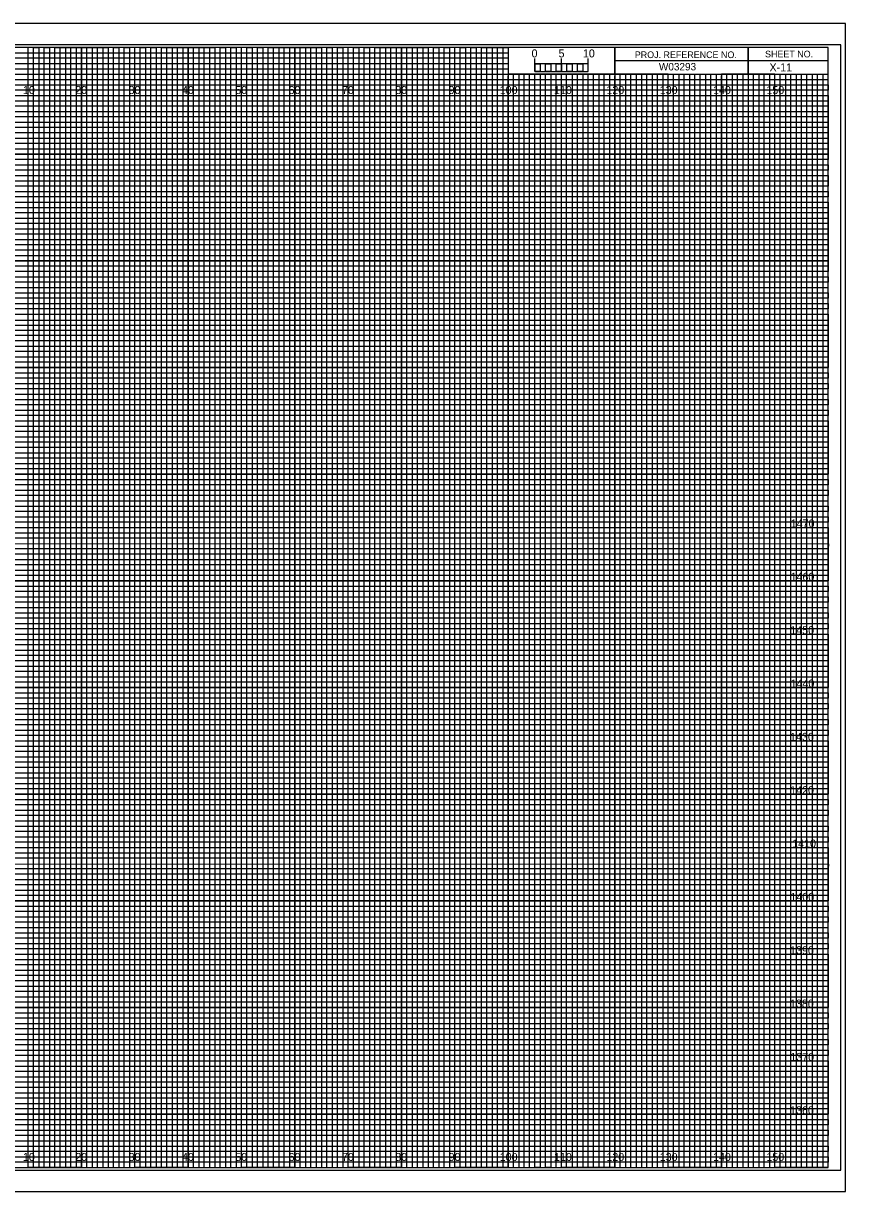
# Model space of a CAD drawing. Extents: x -13 to 323, y -5 to 215.
# Drawn here: x 169.1 to 323.3, y -4.5 to 214.5 of the extents above; entities that cross this region are included whole.
import ezdxf

# ---------------------------------------------------------------- set-up
doc = ezdxf.new("R2010")
doc.units = 0
for name, color, linetype in [('Exist Cross Section Cell', 7, 'Continuous'), ('Exist XS Center Line Elevation Label', 7, 'Continuous'), ('Exist XS Ground Line', 7, 'Continuous'), ('Prop XS EOT Tick Mark', 7, 'Continuous'), ('Prop XS Finish Grade', 7, 'Continuous'), ('Prop XS Finish Grade Pavement', 7, 'Continuous'), ('Prop XS Retaining Wall', 7, 'Continuous'), ('Prop XS SE Text', 7, 'Continuous'), ('Prop XS Side Slope Text', 7, 'Continuous'), ('Prop XS SS Elevation Text', 7, 'Continuous'), ('Prop XS Subgrade Earthwork', 7, 'Continuous'), ('Prop XSC Text', 7, 'Continuous'), ('Scratch_Level_0', 7, 'Continuous'), ('Scratch_Level_5', 7, 'Continuous'), ('Typical Curb CELL', 7, 'Continuous')]:
    doc.layers.add(name, color=color, linetype=linetype)

msp = doc.modelspace()

# ---------------------------------------------------------------- linework, layer by layer
at = {"layer": 'Exist Cross Section Cell'}
for points in [[(165, 0), (175, 0), (175, 210), (185, 210), (185, 0), (195, 0), (195, 210), (205, 210), (205, 0), (215, 0), (215, 210), (225, 210), (225, 0), (235, 0), (235, 210), (245, 210), (245, 0), (255, 0), (255, 210), (259.93, 210), (260, 210), (260, 205), (264.99, 205), (264.99, 0), (275, 0), (275, 205), (285, 205), (285, 0), (295, 0), (295, 205), (305, 205), (305, 0), (315, 0), (315, 205)], [(0, 205), (275, 205)], [(0, 185), (320, 185), (320, 195), (0, 195)], [(0, 165), (320, 165), (320, 175), (0, 175)], [(0, 145), (320, 145), (320, 155), (0, 155)], [(0, 125), (320, 125), (320, 135), (0, 135)], [(0, 105), (320, 105), (320, 115), (0, 115)], [(0, 85), (320, 85), (320, 95), (0, 95)], [(0, 65), (320, 65), (320, 75), (0, 75)], [(0, 45), (320, 45), (320, 55), (0, 55)], [(0, 25), (320, 25), (320, 35), (0, 35)], [(0, 5), (320, 5), (320, 15), (0, 15)]]:
    msp.add_lwpolyline(points, dxfattribs=at)
at = {"layer": 'Exist XS Center Line Elevation Label'}
for p, q in [((170, 210), (160, 210)), ((170, 0), (170, 210)), ((190, 210), (180, 210)), ((180, 210), (180, 0)), ((190, 0), (190, 210)), ((210, 210), (200, 210)), ((200, 210), (200, 0)), ((210, 0), (210, 210)), ((230, 210), (220, 210)), ((220, 210), (220, 0)), ((230, 0), (230, 210)), ((250, 210), (240, 210)), ((240, 210), (240, 0)), ((250, 0), (250, 210)), ((260, 210), (260, 0)), ((270, 0), (270, 205)), ((290, 205), (280, 205)), ((280, 205), (280, 0)), ((290, 0), (290, 205)), ((310, 205), (300, 205)), ((300, 205), (300, 0)), ((310, 0), (310, 205)), ((180, 0), (170, 0)), ((200, 0), (190, 0)), ((220, 0), (210, 0)), ((240, 0), (230, 0)), ((260, 0), (250, 0)), ((280, 0), (270, 0)), ((300, 0), (290, 0)), ((320, 0), (310, 0)), ((320, 0), (320, 0))]:
    msp.add_line(p, q, dxfattribs=at)
for points in [[(0, 200), (320, 200), (320, 190), (0, 190)], [(0, 180), (320, 180), (320, 170), (0, 170)], [(0, 160), (320, 160), (320, 150), (0, 150)], [(0, 140), (320, 140), (320, 130), (0, 130)], [(0, 120), (320, 120), (320, 110), (0, 110)], [(0, 100), (320, 100), (320, 90), (0, 90)], [(0, 80), (320, 80), (320, 70), (0, 70)], [(0, 60), (320, 60), (320, 50), (0, 50)], [(0, 40), (320, 40), (320, 30), (0, 30)], [(0, 20), (320, 20), (320, 10), (0, 10)]]:
    msp.add_lwpolyline(points, dxfattribs=at)
at = {"layer": 'Prop XS EOT Tick Mark'}
for p, q in [((170, 0), (170, 210)), ((180, 0), (180, 210)), ((190, 0), (190, 210)), ((200, 0), (200, 210)), ((210, 0), (210, 210)), ((220, 0), (220, 210)), ((230, 0), (230, 210)), ((240, 0), (240, 210)), ((250, 0), (250, 210)), ((260, 0), (260, 204.69)), ((270, 0), (270, 204.69)), ((280, 0), (280, 204.69)), ((290, 0), (290, 204.69)), ((300, 0), (300, 204.69)), ((310, 0), (310, 204.69)), ((0, 200), (320, 200)), ((0, 190), (320, 190)), ((0, 180), (320, 180)), ((0, 170), (320, 170)), ((0, 160), (320, 160)), ((0, 150), (320, 150)), ((0, 140), (320, 140)), ((0, 130), (320, 130)), ((0, 120), (320, 120)), ((0, 110), (320, 110)), ((0, 100), (320, 100)), ((0, 90), (320, 90)), ((0, 80), (320, 80)), ((0, 70), (320, 70)), ((0, 60), (320, 60)), ((0, 50), (320, 50)), ((0, 40), (320, 40)), ((0, 30), (320, 30)), ((0, 20), (320, 20)), ((0, 10), (320, 10))]:
    msp.add_line(p, q, dxfattribs=at)
at = {"layer": 'Prop XS Finish Grade Pavement'}
msp.add_lwpolyline([(-13.4, -4.5), (323.3, -4.5), (323.3, 214.5), (-13.4, 214.5)], close=True, dxfattribs=at)
at = {"layer": 'Prop XS SE Text'}
for p, q in [((265, 205.49), (265, 207.9)), ((265, 206.9), (265, 207.9)), ((270, 205.49), (270, 207.9)), ((275, 205.49), (275, 207.9)), ((275, 206.9), (275, 207.9))]:
    msp.add_line(p, q, dxfattribs=at)
for points in [[(275, 206.9), (265, 206.9), (265, 205.49), (275, 205.49)], [(265, 206.9), (266, 206.9), (266, 205.49), (265, 205.49)], [(267, 206.9), (268, 206.9), (268, 205.49), (267, 205.49)], [(269, 206.9), (270, 206.9), (270, 205.49), (269, 205.49)], [(271, 206.9), (272, 206.9), (272, 205.49), (271, 205.49)], [(273, 206.9), (274, 206.9), (274, 205.49), (273, 205.49)]]:
    msp.add_lwpolyline(points, close=True, dxfattribs=at)
at = {"layer": 'Prop XS Subgrade Earthwork'}
msp.add_lwpolyline([(-10.8, -0.5), (322.4, -0.5), (322.4, 210.5), (-10.8, 210.5)], close=True, dxfattribs=at)
at = {"layer": 'Prop XSC Text'}
for p, q in [((267, 205), (266.01, 205)), ((266.01, 205), (266.01, 0)), ((267, 0), (267, 205)), ((269, 205), (268, 205)), ((268, 205), (268, 0)), ((269, 0), (269, 205)), ((266.01, 0), (265, 0)), ((268, 0), (267, 0))]:
    msp.add_line(p, q, dxfattribs=at)
for points in [[(170, 0), (171, 0), (171, 210), (172, 210), (172, 0)], [(172, 0), (173, 0), (173, 210), (174, 210), (174, 0)], [(175, 0), (176, 0), (176, 210), (177, 210), (177, 0)], [(177, 0), (178, 0), (178, 210), (179, 210), (179, 0)], [(180, 0), (181, 0), (181, 210), (182, 210), (182, 0)], [(182, 0), (183, 0), (183, 210), (184, 210), (184, 0)], [(185, 0), (186, 0), (186, 210), (187, 210), (187, 0)], [(187, 0), (188, 0), (188, 210), (189, 210), (189, 0)], [(190, 0), (191, 0), (191, 210), (192, 210), (192, 0)], [(192, 0), (193, 0), (193, 210), (194, 210), (194, 0)], [(195, 0), (196, 0), (196, 210), (197, 210), (197, 0)], [(197, 0), (198, 0), (198, 210), (199, 210), (199, 0)], [(200, 0), (201, 0), (201, 210), (202, 210), (202, 0)], [(202, 0), (203, 0), (203, 210), (204, 210), (204, 0)], [(205, 0), (206, 0), (206, 210), (207, 210), (207, 0)], [(207, 0), (208, 0), (208, 210), (209, 210), (209, 0)], [(210, 0), (211, 0), (211, 210), (212, 210), (212, 0)], [(212, 0), (213, 0), (213, 210), (214, 210), (214, 0)], [(215, 0), (216, 0), (216, 210), (217, 210), (217, 0)], [(217, 0), (218, 0), (218, 210), (219, 210), (219, 0)], [(220, 0), (221, 0), (221, 210), (222, 210), (222, 0)], [(222, 0), (223, 0), (223, 210), (224, 210), (224, 0)], [(225, 0), (226, 0), (226, 210), (227, 210), (227, 0)], [(227, 0), (228, 0), (228, 210), (229, 210), (229, 0)], [(230, 0), (231, 0), (231, 210), (232, 210), (232, 0)], [(232, 0), (233, 0), (233, 210), (234, 210), (234, 0)], [(235, 0), (236, 0), (236, 210), (237, 210), (237, 0)], [(237, 0), (238, 0), (238, 210), (239, 210), (239, 0)], [(240, 0), (241, 0), (241, 210), (242, 210), (242, 0)], [(242, 0), (243, 0), (243, 210), (244, 210), (244, 0)], [(245, 0), (246, 0), (246, 210), (247, 210), (247, 0)], [(247, 0), (248, 0), (248, 210), (249, 210), (249, 0)], [(250, 0), (251, 0), (251, 210), (252, 210), (252, 0)], [(252, 0), (253, 0), (253, 210), (254, 210), (254, 0)], [(255, 0), (256, 0), (256, 210), (257, 210), (257, 0)], [(257, 0), (258, 0), (258, 210), (259, 210), (259, 0)], [(260, 0), (261, 0), (261, 205), (262.02, 205), (262.02, 0)], [(262, 0), (263, 0), (263, 205), (263.99, 205), (263.99, 0)], [(270, 0), (270.98, 0), (270.98, 205), (272, 205), (272, 0)], [(272, 0), (273, 0), (273, 205), (274.05, 205), (274.05, 0)], [(275, 0), (276, 0), (276, 205), (277, 205), (277, 0)], [(277, 0), (278, 0), (278, 205), (279, 205), (279, 0)], [(280, 0), (281, 0), (281, 205), (282, 205), (282, 0)], [(282, 0), (283, 0), (283, 205), (284, 205), (284, 0)], [(285, 0), (286, 0), (286, 205), (287, 205), (287, 0)], [(287, 0), (288, 0), (288, 205), (289, 205), (289, 0)], [(290, 0), (291, 0), (291, 205), (292, 205), (292, 0)], [(292, 0), (293, 0), (293, 205), (294, 205), (294, 0)], [(295, 0), (296, 0), (296, 205), (297, 205), (297, 0)], [(297, 0), (298, 0), (298, 205), (299, 205), (299, 0)], [(300, 0), (301, 0), (301, 205), (302, 205), (302, 0)], [(302, 0), (303, 0), (303, 205), (304, 205), (304, 0)], [(305, 0), (306, 0), (306, 205), (307, 205), (307, 0)], [(307, 0), (308, 0), (308, 205), (309, 205), (309, 0)], [(310, 0), (311, 0), (311, 205), (312, 205), (312, 0)], [(312, 0), (313, 0), (313, 205), (314, 205), (314, 0)], [(315, 0), (316, 0), (316, 205), (317, 205), (317, 0)], [(317, 0), (318, 0), (318, 205), (319, 205), (319, 0)]]:
    msp.add_lwpolyline(points, dxfattribs=at)
at = {"layer": 'Scratch_Level_0'}
for p, q in [((305, 210), (305, 205)), ((305, 205), (305, 210)), ((280, 207.5), (280, 205)), ((320, 207.49), (280, 207.49)), ((280, 205), (320, 205))]:
    msp.add_line(p, q, dxfattribs=at)
for points in [[(320, 210), (0, 210), (0, 0), (320, 0)], [(280, 210), (260, 210), (260, 205.03), (280, 205.03)], [(320, 210), (280, 210), (280, 205), (320, 205)]]:
    msp.add_lwpolyline(points, close=True, dxfattribs=at)
at = {"layer": 'Scratch_Level_5'}
for p, q in [((0, 209), (260, 209)), ((260, 209), (260, 207.98)), ((260, 207.98), (0, 207.98)), ((0, 207), (260, 207)), ((260, 205.89), (0, 205.89)), ((260, 207), (260, 205.89)), ((0, 204), (320, 204))]:
    msp.add_line(p, q, dxfattribs=at)
for points in [[(0, 203), (270, 203), (320, 203), (320, 202), (0, 202)], [(0, 201), (320, 201), (320, 199), (0, 199)], [(0, 198), (320, 198), (320, 197), (0, 196.98)], [(0, 196), (320, 196), (320, 194), (0, 194)], [(0, 193), (320, 193), (320, 192), (0, 192)], [(0, 191), (320, 191), (320, 189), (0, 189)], [(0, 188), (320, 188), (320, 187), (0, 187)], [(0, 186), (320, 186), (320, 184), (0, 184)], [(0, 183), (320, 183), (320, 182), (0, 182)], [(0, 181), (320, 181), (320, 179), (0, 179)], [(0, 178), (320, 178), (320, 177), (0, 177)], [(0, 176), (320, 176), (320, 173.95), (320, 173), (320, 172), (0, 172)], [(0, 174), (320, 174), (320, 173), (0, 173)], [(0, 171), (320, 171), (320, 169), (0, 169.03)], [(0, 169.03), (320, 169), (320, 168), (0, 168)], [(0, 167), (320, 167), (320, 166), (0, 166)], [(0, 164), (320, 164), (320, 163), (0, 163)], [(0, 162), (320, 162), (320, 161), (0, 161)], [(-0.07, 158.89), (320, 158.89), (320, 157.88), (-0.07, 157.88)], [(0, 157), (320, 157), (320, 156), (0, 156)], [(0, 154), (320, 154), (320, 153), (0, 153)], [(0, 152), (320, 152), (320, 151), (0, 151)], [(0, 149), (320, 149), (320, 148), (0, 148)], [(0, 147), (320, 147), (320, 146), (0, 146)], [(0, 144), (320, 144), (320, 143), (0, 143)], [(0, 142), (320, 142), (320, 141), (0, 141)], [(0, 139), (320, 139), (319.99, 137.98), (0, 138)], [(0, 137), (320, 137), (320, 136), (0, 136)], [(0, 134), (320, 134), (320, 133), (0, 133)], [(0, 132), (320, 132), (320, 131), (0, 131)], [(0, 129), (320, 129), (320, 128), (0, 128)], [(0, 127), (320, 127), (320, 126), (0, 126)], [(0, 124), (320, 124), (320, 123), (0, 123)], [(0, 122), (320, 122), (320, 121), (0, 121)], [(0, 119), (320, 119), (320, 118), (0, 118)], [(0, 116.99), (320.07, 116.91), (320, 116), (0, 116)], [(0, 114), (320, 114), (320, 113), (0, 113)], [(0, 112), (320, 112), (320, 111), (0, 111)], [(0, 109), (320, 109), (320, 108), (0, 108)], [(0, 107), (320, 107), (320, 106), (0, 106)], [(0, 104), (320, 104), (320, 103), (0, 103)], [(0, 102), (320, 102), (320, 101), (0, 101)], [(0, 99), (320, 99), (320, 98), (0, 98)], [(0, 97), (320, 97), (320, 96), (0, 96)], [(0, 94), (320, 94), (320, 93), (0, 93)], [(0, 92), (320, 92), (320, 91), (0, 91)], [(0, 89), (320, 89), (320, 88), (0, 88)], [(0, 87), (320, 87), (320, 86), (0, 86)], [(0, 84), (320, 84), (320, 83), (0, 83)], [(0, 82), (320, 82), (320, 81), (0, 81)], [(0, 79), (320, 79), (319.99, 77.98), (0, 78)], [(0, 77), (320, 77), (320, 76), (0, 76)], [(0, 74), (320, 74), (320, 73), (0, 73)], [(0, 72), (320, 72), (320, 71), (0, 71)], [(0, 69), (320, 69), (320, 68), (0, 68)], [(0, 67), (320, 67), (320, 66), (0, 66)], [(0, 64), (320, 64), (320, 63), (0, 63)], [(0, 62), (320, 62), (320, 61), (0, 61)], [(0, 59), (320, 59), (320, 58), (0, 58)], [(0, 56.99), (320.07, 56.91), (320, 56), (0, 56)], [(0, 54), (320, 54), (320, 53), (0, 53)], [(0, 52), (320, 52), (320, 51), (0, 51)], [(0, 49), (320, 49), (320, 48), (0, 48)], [(0, 47), (320, 47), (320, 46), (0, 46)], [(0, 44), (320, 44), (320, 43), (0, 43)], [(0, 42), (320, 42), (320, 41), (0, 41)], [(0, 39), (320, 39), (320, 38), (0, 38)], [(0, 37), (320, 37), (320, 36), (0, 36)], [(0, 34), (320, 34), (320, 33), (0, 33)], [(0, 32), (320, 32), (320, 31), (0, 31)], [(0, 29), (320, 29), (320, 28), (0, 28)], [(0, 27), (320, 27), (320, 26), (0, 26)], [(0, 24), (320, 24), (320, 23), (0, 23)], [(0, 22), (320, 22), (320, 21), (0, 21)], [(0, 19), (320, 19), (320, 18), (0, 18)], [(0, 17), (320, 17), (320, 16), (0, 16)], [(0, 14), (320, 14), (320, 13), (0, 13)], [(0, 12), (320, 12), (320, 11), (0, 11)], [(0, 9), (320, 9), (320, 8), (0, 8)], [(0, 7), (320, 7), (320, 6), (0, 6)], [(0, 4), (320, 4), (320, 3), (0, 3)], [(0, 2), (320, 2), (320, 1), (0, 1)]]:
    msp.add_lwpolyline(points, dxfattribs=at)
at = {"layer": 'Typical Curb CELL'}
for p, q in [((323.3, 214.5), (-13.4, 214.5)), ((-13.4, -4.5), (323.3, -4.5))]:
    msp.add_line(p, q, dxfattribs=at)

# ---------------------------------------------------------------- texts
at = {"layer": 'Exist XS Ground Line'}
for s, p in [('10', (169.04, 201.25)), ('20', (178.86, 201.25)), ('30', (188.86, 201.25)), ('40', (198.86, 201.25)), ('50', (208.86, 201.25)), ('60', (218.86, 201.25)), ('70', (228.86, 201.25)), ('80', (238.86, 201.25)), ('90', (248.86, 201.25)), ('100', (258.44, 201.25)), ('110', (268.62, 201.25)), ('120', (278.44, 201.25)), ('130', (288.44, 201.25)), ('140', (298.44, 201.25)), ('150', (308.44, 201.25)), ('10', (169.04, 1.25)), ('20', (178.86, 1.25)), ('30', (188.86, 1.25)), ('40', (198.86, 1.25)), ('50', (208.86, 1.25)), ('60', (218.86, 1.25)), ('70', (228.86, 1.25)), ('80', (238.86, 1.25)), ('90', (248.86, 1.25)), ('100', (258.44, 1.25)), ('110', (268.62, 1.25)), ('120', (278.44, 1.25)), ('130', (288.44, 1.25)), ('140', (298.44, 1.25)), ('150', (308.44, 1.25))]:
    msp.add_text(s, height=1.5, dxfattribs=at).set_placement(p)
at = {"layer": 'Prop XS Finish Grade'}
for s, p in [('1470', (313, 120)), ('1460', (312.97, 110)), ('1450', (312.92, 100)), ('1440', (312.97, 90)), ('1430', (312.89, 80)), ('1420', (312.9, 70)), ('1410', (313.28, 60)), ('1400', (312.95, 50)), ('1390', (312.89, 40)), ('1380', (312.86, 30)), ('1370', (312.92, 20)), ('1360', (312.89, 10))]:
    msp.add_text(s, height=1.5, dxfattribs=at).set_placement(p)
at = {"layer": 'Prop XS Retaining Wall'}
msp.add_text('X-11', height=1.5, dxfattribs=at).set_placement((309.02, 205.5))
at = {"layer": 'Prop XS SE Text'}
msp.add_text('0', height=1.5, dxfattribs=at).set_placement((264.41, 208.12))
at = {"layer": 'Prop XS Side Slope Text'}
msp.add_text('W03293', height=1.4, dxfattribs=at).set_placement((288.29, 205.68))
at = {"layer": 'Prop XS SS Elevation Text'}
for s, p in [('5', (269.47, 208.12)), ('10', (274.04, 208.12))]:
    msp.add_text(s, height=1.5, dxfattribs=at).set_placement(p)
at = {"layer": 'Scratch_Level_0'}
for s, p in [('PROJ. REFERENCE NO.', (283.77, 207.99)), ('SHEET NO.', (308.19, 208.12))]:
    msp.add_text(s, height=1.25, dxfattribs=at).set_placement(p)

doc.saveas('drawing.dxf')
